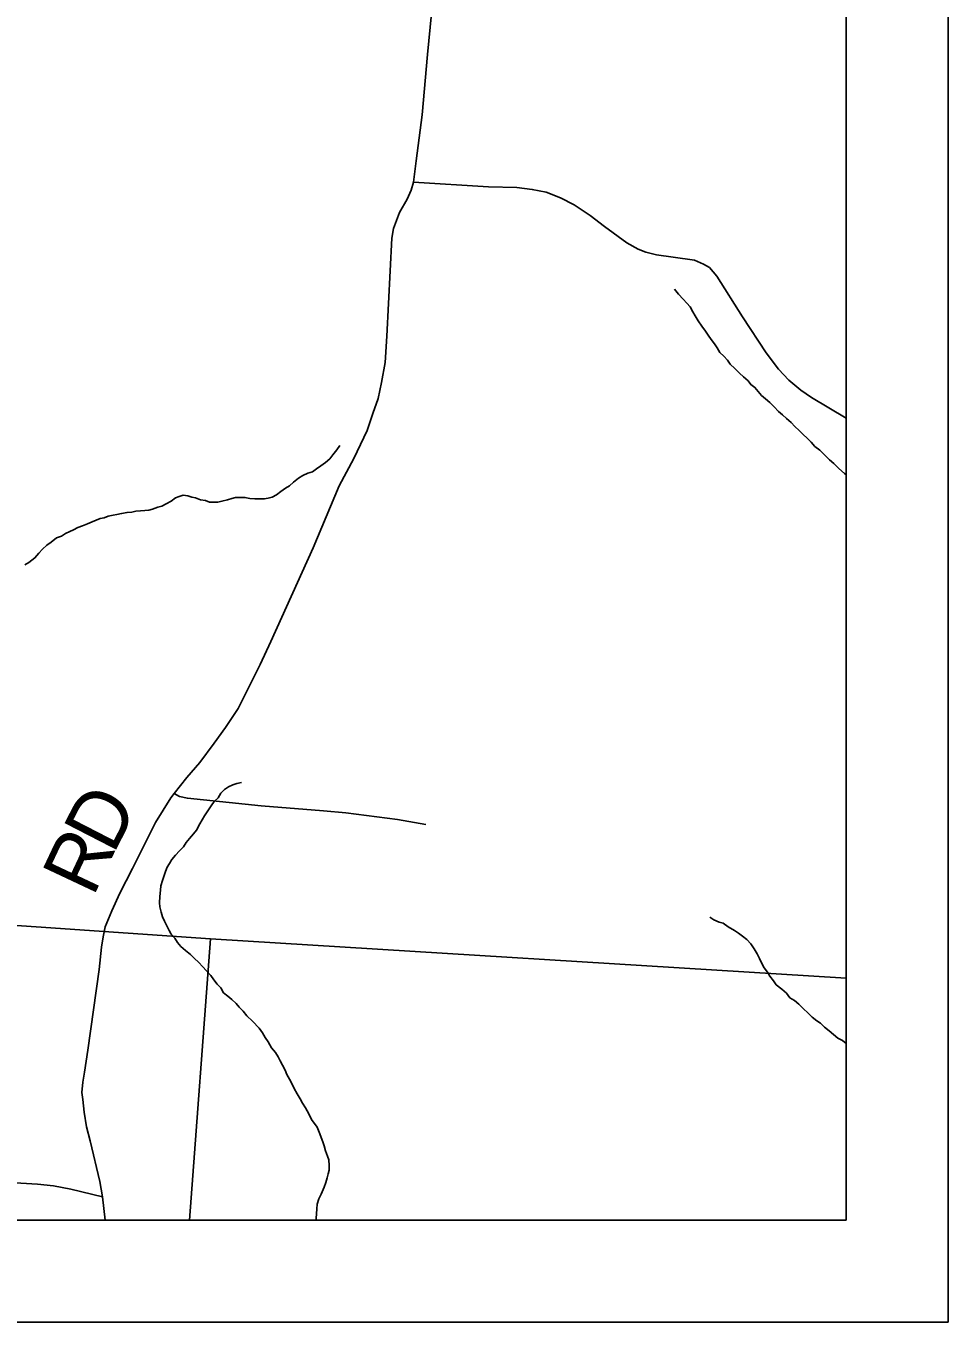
# Model space of a CAD drawing. Extents: x -8.2 to 34, y 0 to 22.
# Drawn here: x 8.096 to 9, y 14 to 15.27 of the extents above; entities that cross this region are included whole.
import ezdxf

# ---------------------------------------------------------------- set-up
doc = ezdxf.new("R2010")
doc.units = 0
for name, color, linetype in [('GM_X_Corporation', 7, 'Continuous'), ('GM_X_County_Road', 7, 'Continuous'), ('GM_X_County_Road_Text', 7, 'Continuous'), ('GM_X_Minor_River', 7, 'Continuous'), ('GM_X_Township_Road', 7, 'Continuous'), ('SH_Data', 7, 'Continuous')]:
    doc.layers.add(name, color=color, linetype=linetype)

msp = doc.modelspace()

# ---------------------------------------------------------------- linework, layer by layer
at = {"layer": 'GM_X_Corporation'}
for points in [[(4.1481, 14.1), (8.9, 14.1), (8.9, 15.3663), (8.5054, 15.392), (7.8479, 15.4343), (7.082, 15.4841), (6.7558, 15.5053), (6.7389, 15.5064), (6.2987, 15.5287), (5.4088, 15.5882), (4.4836, 15.6492), (4.4152, 15.6505), (4.2922, 15.6569), (4.2674, 15.658), (4.2558, 15.6585), (4.2352, 15.4906), (4.2113, 15.0848), (4.1846, 14.6878), (4.1741, 14.5315), (4.1604, 14.3288)], [(7.2372, 14.1), (8.2568, 14.1), (8.2775, 14.3753), (7.2616, 14.4454)], [(8.2568, 14.1), (8.9, 14.1), (8.9, 14.3369), (8.2775, 14.3753)]]:
    msp.add_lwpolyline(points, close=True, dxfattribs=at)
at = {"layer": 'GM_X_County_Road'}
msp.add_lwpolyline([(8.174, 14.1), (8.1715, 14.1228), (8.1689, 14.1377), (8.1593, 14.1777), (8.1557, 14.1913), (8.1534, 14.2058), (8.1522, 14.218), (8.1514, 14.225), (8.1522, 14.2349), (8.1539, 14.2449), (8.157, 14.2665), (8.1681, 14.3455), (8.1704, 14.3673), (8.1721, 14.3773), (8.1742, 14.3872), (8.1807, 14.4029), (8.1886, 14.4202), (8.2008, 14.4445), (8.2236, 14.4894), (8.2385, 14.5135), (8.2418, 14.5177), (8.254, 14.5334), (8.2668, 14.5482), (8.281, 14.5673), (8.2919, 14.5824), (8.3045, 14.601), (8.3172, 14.6266), (8.326, 14.6442), (8.3365, 14.6668), (8.3778, 14.7585), (8.4035, 14.8191), (8.4178, 14.8461), (8.431, 14.8735), (8.4364, 14.8901), (8.4417, 14.9047), (8.445, 14.9204), (8.4484, 14.9399), (8.45, 14.9657), (8.4551, 15.0618), (8.4567, 15.0713), (8.4626, 15.087), (8.4701, 15.1002), (8.4739, 15.1088), (8.4762, 15.1167), (8.4787, 15.1375), (8.4846, 15.1827), (8.49, 15.2418), (8.4924, 15.2686), (8.4953, 15.2956)], dxfattribs=at)
at = {"layer": 'GM_X_Minor_River'}
for points in [[(8.732, 15.0119), (8.7358, 15.007), (8.7403, 15.0021), (8.7441, 14.9983), (8.7472, 14.9945), (8.7499, 14.9896), (8.7521, 14.9858), (8.7552, 14.9809), (8.7586, 14.9755), (8.7624, 14.9706), (8.7651, 14.9668), (8.7678, 14.9627), (8.7712, 14.9585), (8.7739, 14.9543), (8.7765, 14.9498), (8.7804, 14.9464), (8.7838, 14.9422), (8.7865, 14.9384), (8.791, 14.9343), (8.7956, 14.9297), (8.7994, 14.926), (8.804, 14.9222), (8.8066, 14.9184), (8.8108, 14.9157), (8.8139, 14.9116), (8.8173, 14.9078), (8.8211, 14.9044), (8.8253, 14.901), (8.8295, 14.8965), (8.834, 14.8919), (8.8378, 14.8889), (8.8417, 14.8851), (8.8462, 14.8813), (8.85, 14.8775), (8.8542, 14.8734), (8.858, 14.8696), (8.8618, 14.8658), (8.866, 14.862), (8.8694, 14.8579), (8.8744, 14.8541), (8.8793, 14.8492), (8.8839, 14.8446), (8.8881, 14.8412), (8.893, 14.8363), (8.8984, 14.8314), (8.9, 14.8301)], [(8.4039, 14.8586), (8.4012, 14.8544), (8.3971, 14.8495), (8.3944, 14.8457), (8.3899, 14.8422), (8.3853, 14.8388), (8.3812, 14.8358), (8.3774, 14.8331), (8.3728, 14.8316), (8.3679, 14.8293), (8.3637, 14.8266), (8.3588, 14.8228), (8.3546, 14.8194), (8.3508, 14.8171), (8.3463, 14.8137), (8.3421, 14.8103), (8.3376, 14.808), (8.3338, 14.8072), (8.33, 14.8064), (8.3247, 14.8064), (8.3209, 14.8064), (8.3159, 14.8068), (8.311, 14.8079), (8.3064, 14.8079), (8.3019, 14.8079), (8.2981, 14.8067), (8.2939, 14.8056), (8.2886, 14.8041), (8.2844, 14.8033), (8.2802, 14.8033), (8.2765, 14.8033), (8.2723, 14.8048), (8.2677, 14.8055), (8.2628, 14.8074), (8.259, 14.8081), (8.2552, 14.8093), (8.2506, 14.81), (8.2468, 14.8089), (8.243, 14.8074), (8.2389, 14.8043), (8.2339, 14.8016), (8.2298, 14.7994), (8.2256, 14.7982), (8.2206, 14.7963), (8.2169, 14.7955), (8.2131, 14.7951), (8.2089, 14.7947), (8.2043, 14.7944), (8.2002, 14.7936), (8.1956, 14.7932), (8.1903, 14.792), (8.1857, 14.7913), (8.1819, 14.7905), (8.177, 14.7894), (8.1732, 14.7878), (8.1694, 14.7871), (8.1652, 14.7855), (8.1614, 14.784), (8.1569, 14.7821), (8.152, 14.7802), (8.1474, 14.7783), (8.1432, 14.776), (8.1394, 14.7745), (8.1353, 14.7726), (8.1315, 14.7699), (8.1265, 14.7684), (8.1212, 14.7642), (8.1171, 14.7611), (8.1129, 14.7573), (8.1091, 14.7532), (8.1053, 14.7486), (8.0993, 14.744), (8.0955, 14.7417)], [(8.3076, 14.5287), (8.303, 14.5276), (8.2992, 14.5264), (8.295, 14.5245), (8.2909, 14.5219), (8.2875, 14.5181), (8.2848, 14.5135), (8.281, 14.5101), (8.278, 14.5059), (8.2746, 14.501), (8.2716, 14.496), (8.2693, 14.4919), (8.267, 14.4881), (8.2636, 14.482), (8.2606, 14.4782), (8.2568, 14.4736), (8.2534, 14.4698), (8.2508, 14.4656), (8.247, 14.4618), (8.2432, 14.4573), (8.2394, 14.4531), (8.2371, 14.4493), (8.2349, 14.4455), (8.2334, 14.4413), (8.2315, 14.4364), (8.2303, 14.4326), (8.2288, 14.4273), (8.2285, 14.4231), (8.2277, 14.417), (8.2274, 14.4106), (8.2278, 14.4068), (8.2289, 14.4015), (8.2304, 14.3969), (8.2323, 14.3928), (8.235, 14.3875), (8.2369, 14.3837), (8.2388, 14.3799), (8.2423, 14.3761), (8.2449, 14.3719), (8.2484, 14.3678), (8.2529, 14.364), (8.2579, 14.3602), (8.2617, 14.3561), (8.2655, 14.3526), (8.2697, 14.3481), (8.2731, 14.3443), (8.2777, 14.3394), (8.2807, 14.3352), (8.2838, 14.3311), (8.2876, 14.3273), (8.2902, 14.3227), (8.2944, 14.3193), (8.2982, 14.3159), (8.3024, 14.3122), (8.3055, 14.3084), (8.3093, 14.3046), (8.3131, 14.3), (8.3184, 14.2948), (8.3249, 14.2879), (8.3283, 14.2834), (8.331, 14.2789), (8.3337, 14.2747), (8.3371, 14.2686), (8.3409, 14.2641), (8.3436, 14.2599), (8.3455, 14.2558), (8.3478, 14.2516), (8.3504, 14.2467), (8.352, 14.2425), (8.3546, 14.2379), (8.3569, 14.2338), (8.3592, 14.2289), (8.3623, 14.2236), (8.3653, 14.2186), (8.3676, 14.2145), (8.3703, 14.2099), (8.3737, 14.2039), (8.3764, 14.1986), (8.3817, 14.191), (8.3844, 14.1845), (8.3859, 14.1808), (8.3875, 14.1766), (8.3886, 14.1728), (8.3901, 14.1679), (8.3921, 14.1626), (8.3932, 14.1588), (8.3936, 14.1535), (8.3936, 14.1489), (8.3925, 14.1451), (8.3917, 14.1413), (8.3902, 14.1368), (8.3887, 14.1322), (8.3857, 14.1254), (8.3834, 14.1208), (8.3819, 14.1155), (8.3816, 14.111), (8.3812, 14.106), (8.3808, 14.1019), (8.3808, 14.1)], [(8.7666, 14.3968), (8.7704, 14.3941), (8.7757, 14.3919), (8.7795, 14.3907), (8.7845, 14.3873), (8.7906, 14.3835), (8.7948, 14.3809), (8.7986, 14.3779), (8.8028, 14.3749), (8.8066, 14.3707), (8.81, 14.3658), (8.813, 14.3608), (8.8153, 14.3563), (8.8172, 14.3518), (8.8199, 14.3472), (8.823, 14.3427), (8.8252, 14.3389), (8.8291, 14.3343), (8.8317, 14.3305), (8.8371, 14.326), (8.8416, 14.3222), (8.845, 14.3177), (8.8496, 14.315), (8.8538, 14.3113), (8.858, 14.3071), (8.8629, 14.3026), (8.8667, 14.2988), (8.8713, 14.295), (8.8751, 14.2927), (8.8789, 14.2889), (8.8835, 14.2852), (8.8877, 14.2818), (8.8919, 14.278), (8.8964, 14.2757), (8.9, 14.273)]]:
    msp.add_lwpolyline(points, dxfattribs=at)
at = {"layer": 'GM_X_Township_Road'}
for points in [[(8.9, 14.8856), (8.8662, 14.9057), (8.8558, 14.9131), (8.8439, 14.9226), (8.8338, 14.9334), (8.8217, 14.9496), (8.7985, 14.9847), (8.7735, 15.0247), (8.7661, 15.0332), (8.7603, 15.0364), (8.7517, 15.0404), (8.7306, 15.0434), (8.7144, 15.0454), (8.704, 15.0481), (8.6962, 15.051), (8.6854, 15.0573), (8.6633, 15.0733), (8.6492, 15.0841), (8.6336, 15.0944), (8.6201, 15.1014), (8.6062, 15.1068), (8.5925, 15.1097), (8.5774, 15.1115), (8.5497, 15.112), (8.4762, 15.1167)], [(8.2418, 14.5177), (8.2471, 14.5149), (8.2548, 14.5132), (8.3271, 14.5058), (8.3882, 14.5009), (8.4098, 14.499), (8.4607, 14.4923), (8.4884, 14.4873)], [(8.1715, 14.1228), (8.1404, 14.1302), (8.1235, 14.1336), (8.1079, 14.135), (8.0806, 14.1369), (8.0472, 14.1394), (8.0286, 14.1412), (8.0116, 14.1446), (8.0028, 14.1437), (7.995, 14.1394), (7.9873, 14.1345), (7.9753, 14.121), (7.9667, 14.1151), (7.9539, 14.1164), (7.9357, 14.117)]]:
    msp.add_lwpolyline(points, dxfattribs=at)
at = {"layer": 'SH_Data'}
for p, q in [((9, 21), (9, 14)), ((8.9, 20.9), (8.9, 14.1)), ((4.1481, 14.1), (8.9, 14.1)), ((2, 14), (9, 14))]:
    msp.add_line(p, q, dxfattribs=at)

# ---------------------------------------------------------------- texts
at = {"layer": 'GM_X_County_Road_Text'}
for s, rotation, p in [('D', 62.7654, (8.182, 14.4573)), ('R', 64.7931, (8.1623, 14.4155))]:
    msp.add_text(s, height=0.0568, rotation=rotation, dxfattribs=at).set_placement(p)

doc.saveas('drawing.dxf')
